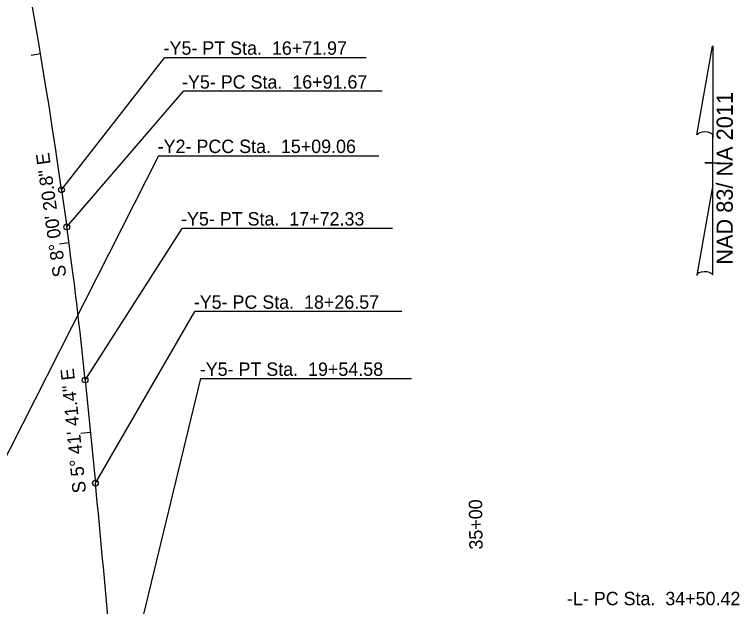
# Model space of a CAD drawing. Extents: x 1616561 to 1622460, y 896726 to 899651.
# Drawn here: x 1619984.9 to 1620364.6, y 898147.7 to 898457.6 of the extents above; entities that cross this region are included whole.
import ezdxf

# ---------------------------------------------------------------- set-up
doc = ezdxf.new("R2010")
doc.units = 0
for name, color, linetype in [('Prop Dimension', 7, 'Continuous'), ('Prop North Arrow NAD83 for Plan Sheets CELL', 7, 'Continuous'), ('Prop Superelevation  Arrow CELL', 7, 'Continuous'), ('Scratch_Level_1', 7, 'Continuous'), ('Sheet Cutting Line CELL', 7, 'Continuous'), ('Sheet North Arrow CELL', 7, 'Continuous')]:
    doc.layers.add(name, color=color, linetype=linetype)

msp = doc.modelspace()

# ---------------------------------------------------------------- linework, layer by layer
at = {"layer": 'Prop North Arrow NAD83 for Plan Sheets CELL'}
for p, q in [((1620342.31, 898394.64), (1620350.52, 898440.98)), ((1620350.57, 898440.98), (1620350.52, 898440.98)), ((1620350.57, 898440.98), (1620350.52, 898440.98)), ((1620350.57, 898440.98), (1620350.56, 898393.18)), ((1620350.55, 898368.38), (1620350.56, 898394.58)), ((1620350.56, 898393.18), (1620350.56, 898394.53)), ((1620346.55, 898379.98), (1620346.5, 898379.98)), ((1620350.1, 898379.98), (1620346.55, 898379.98)), ((1620346.6, 898379.98), (1620354.6, 898379.98)), ((1620350.55, 898368.38), (1620342.18, 898321.14)), ((1620350.58, 898321.33), (1620350.55, 898368.38))]:
    msp.add_line(p, q, dxfattribs=at)
for centre, start_param, end_param in [((1620346.45, 898394.14), 0.216388, 2.908219), ((1620346.42, 898320.97), 0.201328, 3.141593)]:
    msp.add_ellipse(centre, major_axis=(4.23, -0.03), ratio=0.461098, start_param=start_param, end_param=end_param, dxfattribs=at)
at = {"layer": 'Prop Superelevation  Arrow CELL'}
for p, q in [((1619998.56, 898436.99), (1619993.63, 898436.16)), ((1620013.45, 898338.11), (1620008.49, 898337.44)), ((1620024.67, 898238.75), (1620019.69, 898238.26))]:
    msp.add_line(p, q, dxfattribs=at)
at = {"layer": 'Sheet Cutting Line CELL'}
for p, q in [((1620009.56, 898365.88), (1620012.3, 898346.37)), ((1620021.92, 898266.28), (1620027.31, 898212.31))]:
    msp.add_line(p, q, dxfattribs=at)
for centre, radius, start, end in [((1617411.12, 898000.42), 2624.02, 8.00579, 15.75048), ((1618031.8, 898067.82), 2000, 5.69484, 8.00579), ((1615051.98, 897716.16), 5000, 4.22795, 5.69484)]:
    msp.add_arc(centre, radius, start, end, dxfattribs=at)
at = {"layer": 'Sheet North Arrow CELL'}
for p, q in [((1620009.56, 898365.88), (1620063.5, 898434.81)), ((1620169.01, 898434.81), (1620063.5, 898434.81)), ((1620012.3, 898346.37), (1620073.4, 898417.36)), ((1620177.45, 898417.36), (1620073.4, 898417.36)), ((1620060.42, 898383.63), (1619918.08, 898104.12)), ((1620060.42, 898383.63), (1620175.64, 898383.63)), ((1620021.92, 898266.28), (1620072.82, 898345.64)), ((1620182.89, 898345.64), (1620072.82, 898345.64)), ((1620027.31, 898212.31), (1620079.34, 898302.07)), ((1620187.73, 898302.07), (1620079.34, 898302.07)), ((1620038.38, 898084.78), (1620082.55, 898267)), ((1620082.55, 898267), (1620192.89, 898267))]:
    msp.add_line(p, q, dxfattribs=at)
for centre in [(1620009.56, 898365.88), (1620012.3, 898346.37), (1620021.92, 898266.28), (1620027.31, 898212.31)]:
    msp.add_circle(centre, 1.5, dxfattribs=at)

# ---------------------------------------------------------------- texts
at = {"layer": 'Prop Dimension'}
msp.add_text('35+00', height=7, rotation=90.7102, dxfattribs=at).set_placement((1620230.11, 898177.56))
at = {"layer": 'Prop North Arrow NAD83 for Plan Sheets CELL'}
msp.add_text('NAD 83/ NA 2011', height=8.5, rotation=89.9808, dxfattribs=at).set_placement((1620361.06, 898326.63))
at = {"layer": 'Scratch_Level_1'}
for s, rotation, p in [('S 8%%d 00\' 20.8" E', 98.0058, (1620012.14, 898320.65)), ('S 5%%d 41\' 41.4" E', 95.6948, (1620022.45, 898207.42))]:
    msp.add_text(s, height=7, rotation=rotation, dxfattribs=at).set_placement(p)
at = {"layer": 'Sheet North Arrow CELL'}
for s, p in [('-Y5- PT Sta.  16+71.97', (1620063.02, 898436.51)), ('-Y5- PC Sta.  16+91.67', (1620072.66, 898418.76)), ('-Y2- PCC Sta.  15+09.06', (1620059.93, 898385.07)), ('-Y5- PT Sta.  17+72.33', (1620072.15, 898347.12)), ('-Y5- PC Sta.  18+26.57', (1620078.82, 898303.57)), ('-Y5- PT Sta.  19+54.58', (1620081.96, 898268.45)), ('-L- PC Sta.  34+50.42', (1620274.24, 898148.42))]:
    msp.add_text(s, height=7, rotation=360, dxfattribs=at).set_placement(p)

doc.saveas('drawing.dxf')
